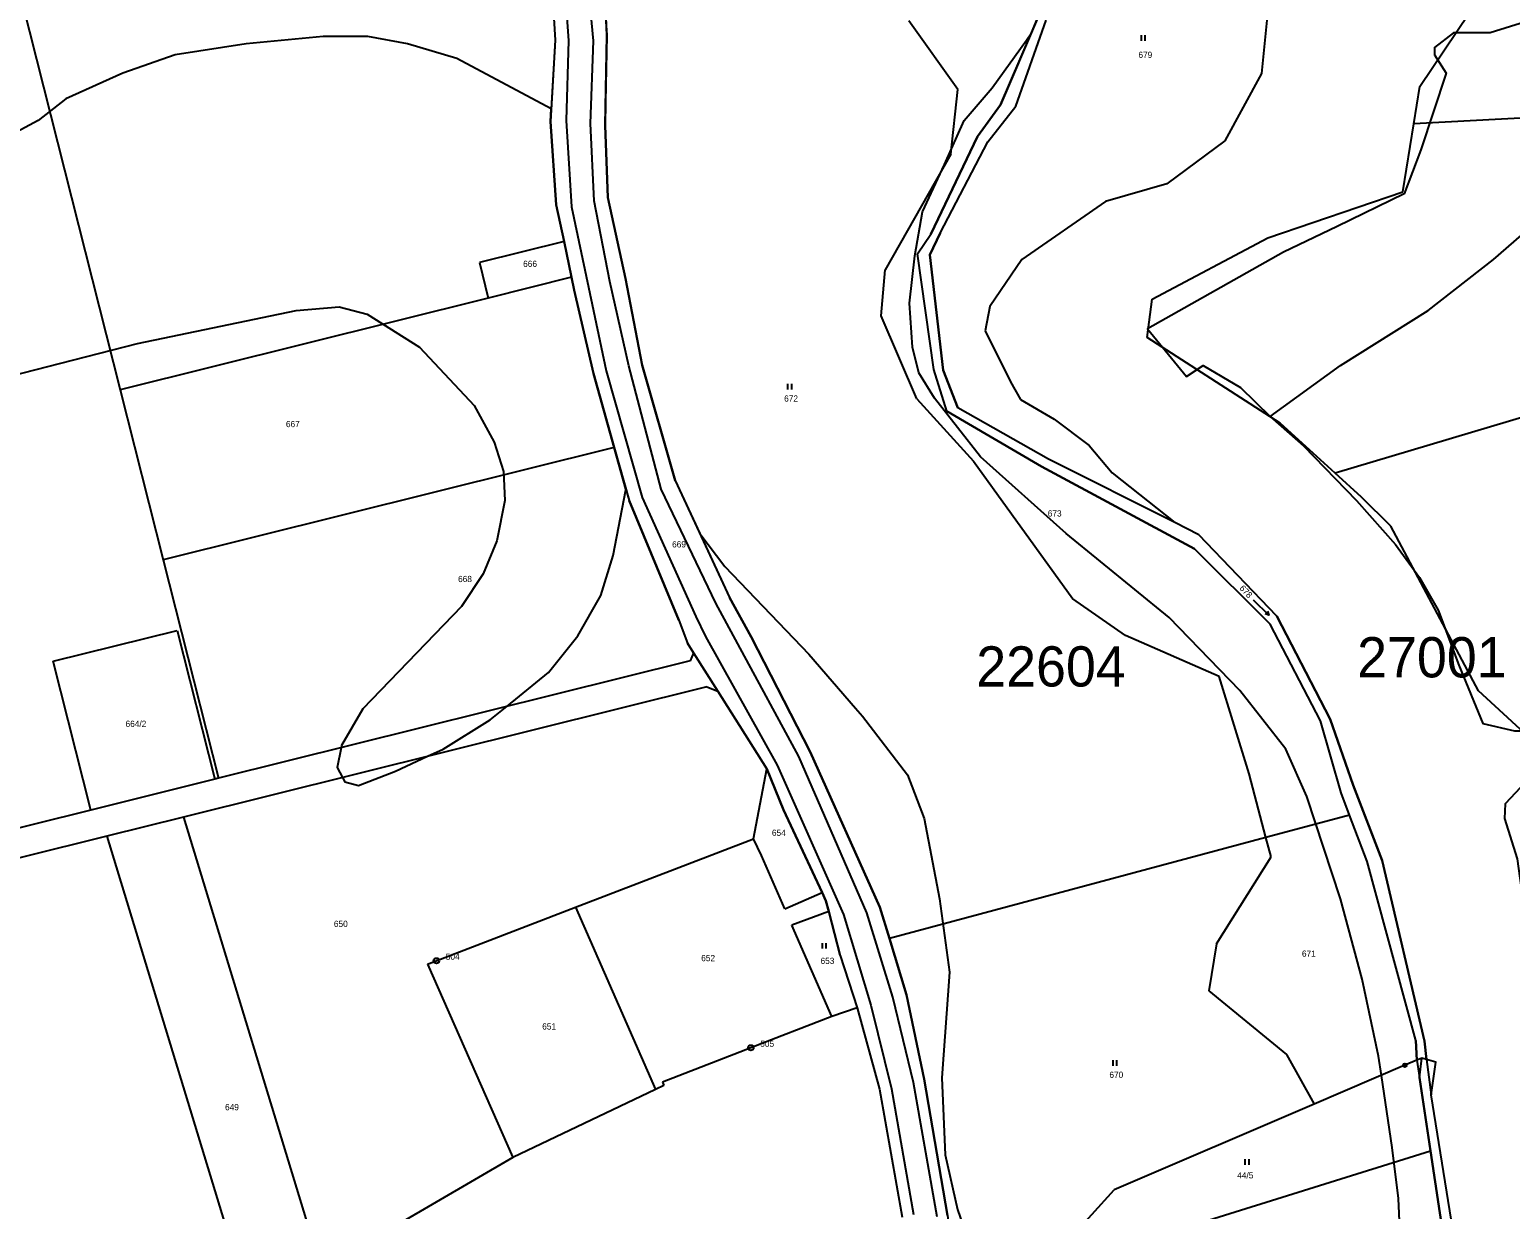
# Model space of a CAD drawing. Extents: x -725765 to -723182, y -1052705 to -1049154.
# Drawn here: x -725226 to -724820.8, y -1050382 to -1050059.1 of the extents above; entities that cross this region are included whole.
import ezdxf

# ---------------------------------------------------------------- set-up
doc = ezdxf.new("R2010")
doc.units = 0
for name, color, linetype in [('Vrstva 1', 7, 'Continuous'), ('Vrstva 17', 7, 'Continuous'), ('Vrstva 18', 7, 'Continuous'), ('Vrstva 25', 7, 'Continuous'), ('Vrstva 4', 7, 'Continuous'), ('Vrstva 52', 7, 'Continuous'), ('Vrstva 53', 7, 'Continuous')]:
    doc.layers.add(name, color=color, linetype=linetype)

msp = doc.modelspace()

# ---------------------------------------------------------------- linework, layer by layer
at = {"layer": 'Vrstva 1'}
for points in [[(-725241.36, -1049999.35), (-725201.29, -1050157.64)], [(-725068.1, -1050060.6), (-725069.02, -1050040.08)], [(-725083.41, -1050042.37), (-725082.24, -1050061.96)], [(-724949.97, -1050055.58), (-724960.32, -1050079.67)], [(-724956.11, -1050080.02), (-724947.83, -1050056.54)], [(-724887.36, -1050055.57), (-724888.93, -1050071.06)], [(-724845.52, -1050074.69), (-724832.09, -1050054.59)], [(-725068.56, -1050085.34), (-725068.1, -1050060.6)], [(-724972.02, -1050075.51), (-724985.38, -1050056.65)], [(-725082.24, -1050061.96), (-725083.52, -1050084.21)], [(-724888.93, -1050071.06), (-724898.89, -1050089.51)], [(-724973.94, -1050093.21), (-724972.02, -1050075.51)], [(-724634.62, -1050073.53), (-724847.19, -1050084.88)], [(-724847.19, -1050084.88), (-724845.52, -1050074.69)], [(-724960.32, -1050079.67), (-724966.62, -1050088.35)], [(-724963.79, -1050089.77), (-724956.11, -1050080.02)], [(-725083.52, -1050084.21), (-725081.89, -1050107.05)], [(-724850.25, -1050103.52), (-724847.19, -1050084.88)], [(-725067.81, -1050105.05), (-725068.56, -1050085.34)], [(-724966.62, -1050088.35), (-724979.36, -1050115.06)], [(-724976.81, -1050114.84), (-724963.79, -1050089.77)], [(-724898.89, -1050089.51), (-724914.84, -1050101.31)], [(-724973.94, -1050093.21), (-724991.93, -1050124.82)], [(-725062.96, -1050127.17), (-725067.81, -1050105.05)], [(-724914.84, -1050101.31), (-724931.63, -1050106.1)], [(-724887.16, -1050116.08), (-724850.25, -1050103.52)], [(-725081.89, -1050107.05), (-725079.77, -1050117.09)], [(-724931.63, -1050106.1), (-724954.49, -1050121.97)], [(-724625.89, -1050108.03), (-724868.77, -1050180.49)], [(-725079.77, -1050117.09), (-725102.96, -1050122.86)], [(-725079.77, -1050117.09), (-725077.7, -1050126.88)], [(-724983.02, -1050120.49), (-724979.36, -1050115.06)], [(-724976.81, -1050114.84), (-724979.69, -1050120.77)], [(-724918.82, -1050132.87), (-724887.16, -1050116.08)], [(-724978.55, -1050152.1), (-724983.02, -1050120.49)], [(-724979.69, -1050120.77), (-724976.03, -1050152.32)], [(-725102.96, -1050122.86), (-725100.51, -1050132.55)], [(-724992.94, -1050137.41), (-724991.93, -1050124.82)], [(-724954.49, -1050121.97), (-724963.26, -1050134.88)], [(-725077.7, -1050126.88), (-725100.51, -1050132.55)], [(-725077.7, -1050126.88), (-725076.96, -1050130.4)], [(-725058.37, -1050150.93), (-725062.96, -1050127.17)], [(-725100.51, -1050132.55), (-725201.29, -1050157.64)], [(-725076.96, -1050130.4), (-725071.67, -1050153.23)], [(-724920.14, -1050143.34), (-724918.82, -1050132.87)], [(-724983.26, -1050160.17), (-724992.94, -1050137.41)], [(-724963.26, -1050134.88), (-724964.55, -1050141.51)], [(-724964.55, -1050141.51), (-724957.54, -1050155.53)], [(-724883.81, -1050166.79), (-724920.14, -1050143.34)], [(-725071.67, -1050153.23), (-725066.05, -1050173.42)], [(-725049.32, -1050182.53), (-725058.37, -1050150.93)], [(-724975, -1050163.48), (-724978.55, -1050152.1)], [(-724976.03, -1050152.32), (-724971.99, -1050162.64)], [(-725201.29, -1050157.64), (-725189.52, -1050204.16)], [(-724957.54, -1050155.53), (-724954.88, -1050160.31)], [(-724983.26, -1050160.17), (-724967.73, -1050177.21)], [(-724954.88, -1050160.31), (-724945.64, -1050165.68)], [(-724975, -1050163.48), (-724949.13, -1050178.68)], [(-724947.18, -1050176.65), (-724971.99, -1050162.64)], [(-724945.64, -1050165.68), (-724936.05, -1050172.87)], [(-724868.77, -1050180.49), (-724883.81, -1050166.79)], [(-725066.05, -1050173.42), (-725189.52, -1050204.16)], [(-725066.05, -1050173.42), (-725061.99, -1050187.99)], [(-724936.05, -1050172.87), (-724929.78, -1050180.43)], [(-724967.73, -1050177.21), (-724940.51, -1050214.9)], [(-724912.63, -1050194.02), (-724947.18, -1050176.65)], [(-724949.13, -1050178.68), (-724907.21, -1050201.2)], [(-724929.78, -1050180.43), (-724912.63, -1050194.02)], [(-724861.55, -1050187.07), (-724868.77, -1050180.49)], [(-725049.32, -1050182.53), (-725034.47, -1050214.49)], [(-725048.34, -1050220.73), (-725061.99, -1050187.99)], [(-724853.45, -1050194.94), (-724861.55, -1050187.07)], [(-724906.04, -1050197.33), (-724912.63, -1050194.02)], [(-724884.67, -1050219.62), (-724906.04, -1050197.33)], [(-724829.49, -1050240.06), (-724853.45, -1050194.94)], [(-724907.21, -1050201.2), (-724886.48, -1050221.83)], [(-725189.52, -1050204.16), (-725174.38, -1050263.97)], [(-725028.58, -1050225.24), (-725034.47, -1050214.49)], [(-724926.11, -1050224.93), (-724940.51, -1050214.9)], [(-725048.34, -1050220.73), (-725046.03, -1050226.98)], [(-724872.7, -1050248.23), (-724886.48, -1050221.83)], [(-724884.67, -1050219.62), (-724870.08, -1050247.81)], [(-725219.62, -1050231.95), (-725185.66, -1050223.51)], [(-725185.66, -1050223.51), (-725175.35, -1050264.21)], [(-725012.45, -1050256.75), (-725028.58, -1050225.24)], [(-724900.5, -1050236.13), (-724926.11, -1050224.93)], [(-725044.35, -1050229.64), (-725046.03, -1050226.98)], [(-725044.35, -1050229.64), (-725045.23, -1050231.81)], [(-725037.72, -1050240.15), (-725044.35, -1050229.64)], [(-725209.31, -1050272.67), (-725219.62, -1050231.95)], [(-725045.23, -1050231.81), (-725174.38, -1050263.97)], [(-725040.73, -1050238.94), (-725183.93, -1050274.59)], [(-725040.73, -1050238.94), (-725037.72, -1050240.15)], [(-724892.29, -1050262.77), (-724900.5, -1050236.13)], [(-725024.32, -1050261.39), (-725037.72, -1050240.15)], [(-724812.36, -1050255.79), (-724829.49, -1050240.06)], [(-724867.1, -1050267.98), (-724872.7, -1050248.23)], [(-724870.08, -1050247.81), (-724863.82, -1050265.84)], [(-724993.31, -1050299.29), (-725012.45, -1050256.75)], [(-725027.89, -1050280.52), (-725024.32, -1050261.39)], [(-725019.69, -1050272.58), (-725024.32, -1050261.39)], [(-724887.67, -1050280.19), (-724892.29, -1050262.77)], [(-725175.35, -1050264.21), (-725209.31, -1050272.67)], [(-725174.38, -1050263.97), (-725175.35, -1050264.21)], [(-724863.82, -1050265.84), (-724855.88, -1050286.44)], [(-724864.79, -1050274.06), (-724867.1, -1050267.98)], [(-725209.31, -1050272.67), (-725321.64, -1050300.63)], [(-725183.93, -1050274.59), (-725204.92, -1050279.81)], [(-725183.93, -1050274.59), (-725146.21, -1050398.37)], [(-725009.09, -1050295.23), (-725019.69, -1050272.58)], [(-724864.79, -1050274.06), (-724887.67, -1050280.19)], [(-724859.95, -1050286.78), (-724864.79, -1050274.06)], [(-725204.92, -1050279.81), (-725415.62, -1050332.26)], [(-725204.92, -1050279.81), (-725165.38, -1050409.56)], [(-725076.63, -1050299.27), (-725027.89, -1050280.52)], [(-725025.75, -1050285.14), (-725027.89, -1050280.52)], [(-724887.67, -1050280.19), (-724990.73, -1050307.79)], [(-724886.26, -1050285.52), (-724887.67, -1050280.19)], [(-725019.38, -1050299.69), (-725025.75, -1050285.14)], [(-724901.2, -1050309.27), (-724886.26, -1050285.52)], [(-724846.68, -1050335.72), (-724859.95, -1050286.78)], [(-724855.88, -1050286.44), (-724844.26, -1050335.94)], [(-725019.38, -1050299.69), (-725009.09, -1050295.23)], [(-725008.13, -1050297.52), (-725009.09, -1050295.23)], [(-725117.11, -1050314.85), (-725076.63, -1050299.27)], [(-725076.63, -1050299.27), (-725054.71, -1050349.13)], [(-725007.31, -1050300.47), (-725008.13, -1050297.52)], [(-724990.73, -1050307.79), (-724993.31, -1050299.29)], [(-725007.31, -1050300.47), (-725017.42, -1050304.16)], [(-725004.19, -1050312.5), (-725007.31, -1050300.47)], [(-725006.47, -1050329.19), (-725017.42, -1050304.16)], [(-724986.04, -1050323.28), (-724990.73, -1050307.79)], [(-724901.2, -1050309.27), (-724903.32, -1050322.18)], [(-725117.11, -1050314.85), (-725093.83, -1050367.81)], [(-725004.19, -1050312.5), (-724999.58, -1050326.84)], [(-724981.17, -1050346.3), (-724986.04, -1050323.28)], [(-724903.32, -1050322.18), (-724882.06, -1050339.62)], [(-724999.58, -1050326.84), (-725006.47, -1050329.19)], [(-724999.58, -1050326.84), (-724993.47, -1050349.06)], [(-725006.47, -1050329.19), (-725028.65, -1050337.74)], [(-724846.68, -1050335.72), (-724846.38, -1050341.13)], [(-724844.26, -1050335.94), (-724843.76, -1050340.91)], [(-725031.66, -1050338.93), (-725052.82, -1050347.19)], [(-725028.65, -1050337.74), (-725031.66, -1050338.93)], [(-724882.06, -1050339.62), (-724874.44, -1050353.15)], [(-724849.63, -1050342.52), (-724874.44, -1050353.15)], [(-724846.38, -1050341.13), (-724849.63, -1050342.52)], [(-724845.03, -1050340.55), (-724846.38, -1050341.13)], [(-724845.67, -1050345.83), (-724845.03, -1050340.55)], [(-724843.76, -1050340.91), (-724845.03, -1050340.55)], [(-724841.18, -1050341.63), (-724843.76, -1050340.91)], [(-724842.44, -1050350.62), (-724841.18, -1050341.63)], [(-725052.48, -1050348.07), (-725054.71, -1050349.13)], [(-725052.82, -1050347.19), (-725052.48, -1050348.07)], [(-724974.8, -1050383.63), (-724981.17, -1050346.3)], [(-724845.67, -1050345.83), (-724842.62, -1050365.92)], [(-725054.71, -1050349.13), (-725093.83, -1050367.81)], [(-724993.47, -1050349.06), (-724987.22, -1050384.11)], [(-724831.39, -1050419.25), (-724842.44, -1050350.62)], [(-724874.44, -1050353.15), (-724929.23, -1050376.61)], [(-725093.83, -1050367.81), (-725146.21, -1050398.37)], [(-724938.14, -1050395.74), (-724842.62, -1050365.92)], [(-724842.62, -1050365.92), (-724838.76, -1050391.39)], [(-724941.4, -1050390.14), (-724929.23, -1050376.61)]]:
    msp.add_lwpolyline(points, dxfattribs=at)
at = {"layer": 'Vrstva 25'}
for points in [[(-724921.74, -1050062.12), (-724921.74, -1050060.62)], [(-724920.7, -1050062.12), (-724920.7, -1050060.62)], [(-725018.51, -1050157.56), (-725018.51, -1050156.06)], [(-725017.47, -1050157.56), (-725017.47, -1050156.06)], [(-724891.2, -1050215.18), (-724886.86, -1050219.32)], [(-724887.24, -1050218.27), (-724886.86, -1050219.32), (-724887.93, -1050218.99)], [(-725009.05, -1050310.59), (-725009.05, -1050309.09)], [(-725008.01, -1050310.59), (-725008.01, -1050309.09)], [(-724929.53, -1050342.65), (-724929.53, -1050341.15)], [(-724928.49, -1050342.65), (-724928.49, -1050341.15)], [(-724893.35, -1050369.73), (-724893.35, -1050368.23)], [(-724892.31, -1050369.73), (-724892.31, -1050368.23)]]:
    msp.add_lwpolyline(points, dxfattribs=at)
for centre, radius in [((-725114.71, -1050313.93), 0.75), ((-725114.71, -1050313.93), 0.032), ((-725028.65, -1050337.74), 0.75), ((-725028.65, -1050337.74), 0.032), ((-724849.63, -1050342.52), 0.5), ((-724849.63, -1050342.52), 0.032)]:
    msp.add_circle(centre, radius, dxfattribs=at)
at = {"layer": 'Vrstva 4'}
for points in [[(-725079.91, -1050043.22), (-725078.6, -1050062.1)], [(-725071.68, -1050062.17), (-725073.53, -1050042.65)], [(-725078.6, -1050062.1), (-725079.22, -1050084)], [(-725072.57, -1050084.81), (-725071.68, -1050062.17)], [(-725079.22, -1050084), (-725077.7, -1050107.61)], [(-725071.57, -1050105.99), (-725072.57, -1050084.81)], [(-725077.7, -1050107.61), (-725073.11, -1050129.54)], [(-725067.25, -1050128.02), (-725071.57, -1050105.99)], [(-725073.11, -1050129.54), (-725068.26, -1050152.48)], [(-725062.04, -1050151.09), (-725067.25, -1050128.02)], [(-725068.26, -1050152.48), (-725058.37, -1050187.14)], [(-725053.15, -1050184.82), (-725062.04, -1050151.09)], [(-725038.22, -1050216.04), (-725053.15, -1050184.82)], [(-725058.37, -1050187.14), (-725043.71, -1050219.67)], [(-725032.23, -1050227.18), (-725038.22, -1050216.04)], [(-725043.71, -1050219.67), (-725041.1, -1050225.17)], [(-725041.1, -1050225.17), (-725021.48, -1050260.41)], [(-725015.53, -1050258.03), (-725032.23, -1050227.18)], [(-724996.92, -1050300.79), (-725015.53, -1050258.03)], [(-725021.48, -1050260.41), (-725003.32, -1050301.25)], [(-725003.32, -1050301.25), (-724995.82, -1050326.05)], [(-724989.81, -1050323.86), (-724996.92, -1050300.79)], [(-724984.14, -1050347.26), (-724989.81, -1050323.86)], [(-724995.82, -1050326.05), (-724990.12, -1050348.93)], [(-724846.38, -1050341.13), (-724845.67, -1050345.83)], [(-724843.76, -1050340.91), (-724842.44, -1050350.62)], [(-724977.7, -1050383.99), (-724984.14, -1050347.26)], [(-724990.12, -1050348.93), (-724984.14, -1050383.34)]]:
    msp.add_lwpolyline(points, dxfattribs=at)
at = {"layer": 'Vrstva 52'}
for points in [[(-724814.04, -1049876.05), (-724813, -1049924), (-724811.5, -1049934), (-724813, -1049944), (-724815.13, -1049953), (-724821.69, -1049977), (-724830.31, -1049995), (-724834.88, -1050018), (-724838.38, -1050044), (-724816.63, -1050057), (-724826.31, -1050060), (-724836.38, -1050060), (-724841.5, -1050064), (-724841.5, -1050066), (-724838.38, -1050071), (-724845.31, -1050092), (-724849.88, -1050104), (-724868.19, -1050113), (-724882.88, -1050120), (-724920.13, -1050141), (-724909.38, -1050154), (-724904.81, -1050151), (-724894.63, -1050157), (-724886.5, -1050165)], [(-724886.5, -1050165), (-724867.31, -1050151), (-724843.31, -1050136), (-724825.38, -1050122), (-724802.38, -1050102), (-724784.38, -1050086), (-724777.5, -1050075), (-724777.5, -1050068), (-724782.38, -1050056), (-724797.38, -1050035), (-724802.38, -1050020), (-724803.38, -1049997), (-724802.38, -1049978), (-724799.38, -1049960), (-724793.38, -1049942), (-724784.38, -1049920), (-724765.19, -1049885.68)], [(-725097.38, -1049960.92), (-725096.89, -1049962.97), (-725095.89, -1049967.35), (-725090.1, -1050004.65), (-725083.41, -1050042.37), (-725082.24, -1050061.96), (-725083.32, -1050080.73)], [(-724929.73, -1050006.76), (-724974.39, -1050014.31), (-724989.11, -1050015.58), (-725000.29, -1050018.07), (-725012.41, -1050018.69), (-725041.64, -1050018.85), (-725073.34, -1050019.52), (-725069.02, -1050040.08), (-725068.22, -1050057.97), (-725068.1, -1050060.6), (-725068.44, -1050078.94), (-725068.56, -1050085.34), (-725067.81, -1050105.05), (-725062.96, -1050127.17), (-725058.37, -1050150.93), (-725049.32, -1050182.53), (-725042.59, -1050197.01)], [(-724951.87, -1050060.01), (-724949.97, -1050055.58), (-724943.69, -1050039.58), (-724941.97, -1050036.66), (-724935.41, -1050031.9)], [(-724831.39, -1050419.25), (-724842.44, -1050350.62), (-724841.18, -1050341.63), (-724843.76, -1050340.91), (-724844.26, -1050335.94), (-724855.88, -1050286.44), (-724863.82, -1050265.84), (-724870.08, -1050247.81), (-724884.67, -1050219.62), (-724906.04, -1050197.33), (-724912.63, -1050194.02), (-724947.18, -1050176.65), (-724971.99, -1050162.64), (-724976.03, -1050152.32), (-724979.69, -1050120.77), (-724976.81, -1050114.84), (-724963.79, -1050089.77), (-724956.11, -1050080.02), (-724947.83, -1050056.54)], [(-724849.63, -1050418), (-724851.38, -1050379), (-724853.13, -1050365), (-724856.08, -1050345.28), (-724856.88, -1050340), (-724861.31, -1050319), (-724867.31, -1050297), (-724876.5, -1050269), (-724882.19, -1050256), (-724894.81, -1050240), (-724914.19, -1050220), (-724942.31, -1050197), (-724965.81, -1050176), (-724978.38, -1050160), (-724982.69, -1050153), (-724984.38, -1050146), (-724985.19, -1050134), (-724983.81, -1050121), (-724981.63, -1050109), (-724975.69, -1050096), (-724970.31, -1050084), (-724962.63, -1050075), (-724953.19, -1050062), (-724951.87, -1050060.01)], [(-724838.76, -1050391.39), (-724842.62, -1050365.92), (-724845.67, -1050345.83), (-724845.03, -1050340.55), (-724846.38, -1050341.13), (-724846.68, -1050335.72), (-724859.95, -1050286.78), (-724864.79, -1050274.06), (-724867.1, -1050267.98), (-724872.7, -1050248.23), (-724886.48, -1050221.83), (-724907.21, -1050201.2), (-724949.13, -1050178.68), (-724975, -1050163.48), (-724978.55, -1050152.1), (-724983.02, -1050120.49), (-724979.36, -1050115.06), (-724966.62, -1050088.35), (-724960.32, -1050079.67), (-724951.87, -1050060.01)], [(-725083.32, -1050080.73), (-725109.13, -1050067), (-725122.63, -1050063), (-725133.5, -1050061), (-725145.69, -1050061), (-725166.81, -1050063), (-725186.19, -1050066), (-725200.5, -1050071), (-725216.13, -1050078), (-725223.69, -1050084), (-725236.88, -1050091)], [(-725062.86, -1050184.86), (-725066.05, -1050173.42), (-725071.67, -1050153.23), (-725076.96, -1050130.4), (-725077.7, -1050126.88), (-725079.77, -1050117.09), (-725081.89, -1050107.05), (-725083.52, -1050084.21), (-725083.32, -1050080.73)], [(-725266.63, -1050163), (-725196.5, -1050145), (-725153.13, -1050136), (-725141.31, -1050135), (-725133.69, -1050137), (-725119.38, -1050146), (-725104.38, -1050162), (-725098.88, -1050172), (-725096.38, -1050180), (-725096, -1050188), (-725098.13, -1050199), (-725101.88, -1050208), (-725107.81, -1050217), (-725134.81, -1050245), (-725140.69, -1050255), (-725140.81, -1050255.61), (-725141.88, -1050261), (-725140.45, -1050263.77), (-725139.81, -1050265), (-725136, -1050266), (-725125.88, -1050262), (-725117.11, -1050257.96), (-725112.88, -1050256), (-725100, -1050248), (-725095.47, -1050244.32), (-725084, -1050235), (-725076, -1050225), (-725069.69, -1050214), (-725066.31, -1050203), (-725062.88, -1050185), (-725062.86, -1050184.86)], [(-724886.5, -1050165), (-724877.38, -1050173), (-724862.88, -1050188), (-724852.19, -1050200), (-724845.63, -1050209), (-724840.5, -1050218), (-724834.88, -1050233), (-724828.31, -1050249), (-724819.63, -1050251), (-724810.5, -1050251), (-724811, -1050259), (-724822.19, -1050271), (-724822.38, -1050275), (-724818.88, -1050286), (-724814.63, -1050317)], [(-725062.86, -1050184.86), (-725061.99, -1050187.99), (-725048.34, -1050220.73), (-725046.03, -1050226.98), (-725044.35, -1050229.64), (-725037.72, -1050240.15), (-725024.32, -1050261.39), (-725019.69, -1050272.58), (-725009.09, -1050295.23), (-725008.13, -1050297.52), (-725007.31, -1050300.47), (-725004.19, -1050312.5), (-724999.58, -1050326.84), (-724993.47, -1050349.06), (-724987.22, -1050384.11)], [(-725042.59, -1050197.01), (-725034.47, -1050214.49), (-725028.58, -1050225.24), (-725012.45, -1050256.75), (-724993.31, -1050299.29), (-724990.73, -1050307.79), (-724986.04, -1050323.28), (-724981.17, -1050346.3), (-724974.8, -1050383.63), (-724970.83, -1050413.34), (-724971.83, -1050413.7), (-724969.28, -1050428.13), (-724952.25, -1050469.19)], [(-725042.59, -1050197.01), (-725035.81, -1050206), (-725012.81, -1050230), (-725000, -1050244.83), (-724998.13, -1050247), (-724985.81, -1050263), (-724981.19, -1050275), (-724977, -1050297), (-724974.31, -1050317), (-724976.38, -1050346), (-724975.5, -1050367), (-724972.13, -1050382), (-724966.88, -1050397), (-724960.83, -1050409.79), (-724959.31, -1050413), (-724943.31, -1050438), (-724934.88, -1050449), (-724926.38, -1050460), (-724894.81, -1050496)]]:
    msp.add_lwpolyline(points, dxfattribs=at)

# ---------------------------------------------------------------- texts
at = {"layer": 'Vrstva 17'}
for s, p in [('504 ', (-725112.14, -1050313.66)), ('505 ', (-725026.08, -1050337.47))]:
    msp.add_text(s, height=1.7, dxfattribs=at).set_placement(p)
at = {"layer": 'Vrstva 18'}
for s, p in [('679', (-724922.58, -1050066.84)), ('666', (-725090.97, -1050124.04)), ('672', (-725019.54, -1050160.9)), ('667', (-725155.89, -1050167.89)), ('673', (-724947.39, -1050192.34)), ('669', (-725050.21, -1050200.81)), ('668', (-725108.78, -1050210.29)), ('664/2', (-725199.78, -1050249.92)), ('654', (-725022.88, -1050279.75)), ('650', (-725142.77, -1050304.67)), ('671', (-724877.82, -1050312.82)), ('652', (-725042.23, -1050314.04)), ('653', (-725009.57, -1050314.8)), ('651', (-725085.75, -1050332.75)), ('670', (-724930.52, -1050345.98)), ('649', (-725172.56, -1050354.84)), ('44/5', (-724895.53, -1050373.49))]:
    msp.add_text(s, height=1.7, dxfattribs=at).set_placement(p)
msp.add_text('678', height=1.7, rotation=314.1025, dxfattribs=at).set_placement((-724895.06, -1050212.11))
at = {"layer": 'Vrstva 53'}
for s, p in [('27001', (-724862.71, -1050236.36)), ('22604', (-724966.95, -1050238.87))]:
    msp.add_text(s, height=11, dxfattribs=at).set_placement(p)

doc.saveas('drawing.dxf')
